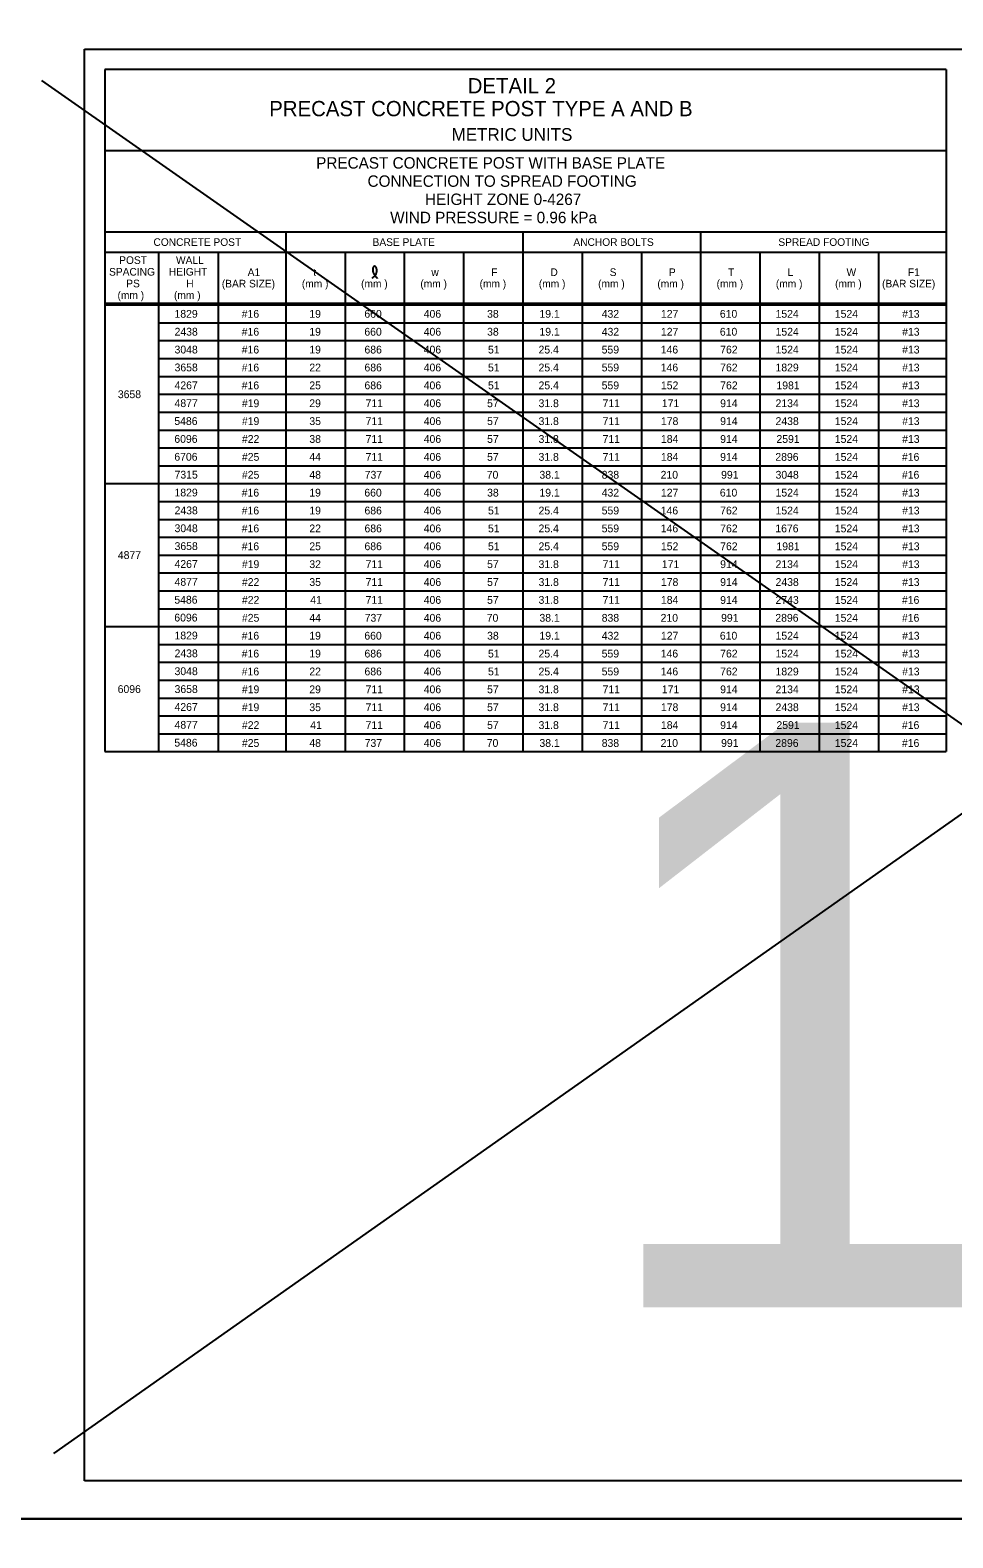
# Model space of a CAD drawing. Extents: x 3351 to 8430, y -3586 to 1457.
# Drawn here: x 5462 to 5825, y -1218 to -624 of the extents above; entities that cross this region are included whole.
import ezdxf

# ---------------------------------------------------------------- set-up
doc = ezdxf.new("R2010")
doc.units = 0
for name, color, linetype in [('1', 7, 'Continuous'), ('2', 7, 'Continuous'), ('PLT-BNDY', 7, 'Continuous')]:
    doc.layers.add(name, color=color, linetype=linetype)

msp = doc.modelspace()

# ---------------------------------------------------------------- linework, layer by layer
at = {"layer": '1'}
for p, q in [((6244.18, -639.77), (5471.21, -1184.55)), ((5491.34, -639.31), (5491.34, -908.06)), ((5822.68, -639.31), (5491.34, -639.31)), ((5822.68, -639.31), (5822.68, -908.06)), ((5466.41, -643.63), (6239.57, -1184.96)), ((5822.68, -671.31), (5491.34, -671.31)), ((5491.34, -703.31), (5822.68, -703.31)), ((5491.34, -703.31), (5559.34, -703.31)), ((5491.34, -703.31), (5559.34, -703.31)), ((5491.34, -703.31), (5559.34, -703.31)), ((5562.68, -703.31), (5562.68, -908.06)), ((5656.01, -703.31), (5656.01, -908.06)), ((5726.01, -703.31), (5726.01, -908.06)), ((5491.34, -711.31), (5822.68, -711.31)), ((5512.68, -908.06), (5512.68, -711.31)), ((5536.01, -711.31), (5536.01, -908.06)), ((5586.01, -711.31), (5586.01, -908.06)), ((5609.34, -711.31), (5609.34, -908.06)), ((5632.68, -711.31), (5632.68, -908.06)), ((5679.34, -711.31), (5679.34, -908.06)), ((5702.68, -711.31), (5702.68, -908.06)), ((5749.34, -711.31), (5749.34, -908.06)), ((5772.68, -711.31), (5772.68, -908.06)), ((5796.01, -711.31), (5796.01, -908.06)), ((5491.34, -731.31), (5822.68, -731.31)), ((5491.34, -732.06), (5822.68, -732.06)), ((5549.33, -735.58), (5549.33, -735.58)), ((5574.34, -735.58), (5574.34, -735.58)), ((5597.68, -735.58), (5597.68, -735.58)), ((5621.01, -735.58), (5621.01, -735.58)), ((5644.34, -735.58), (5644.34, -735.58)), ((5667.68, -735.58), (5667.68, -735.58)), ((5691.01, -735.58), (5691.01, -735.58)), ((5714.34, -735.58), (5714.34, -735.58)), ((5737.67, -735.58), (5737.67, -735.58)), ((5761.01, -735.58), (5761.01, -735.58)), ((5784.34, -735.58), (5784.34, -735.58)), ((5809.33, -735.58), (5809.33, -735.58)), ((5512.68, -739.1), (5822.68, -739.1)), ((5512.68, -746.14), (5822.68, -746.14)), ((5512.68, -753.18), (5822.68, -753.18)), ((5512.68, -760.22), (5822.68, -760.22)), ((5512.68, -767.26), (5822.68, -767.26)), ((5512.68, -774.3), (5822.68, -774.3)), ((5512.68, -781.34), (5822.68, -781.34)), ((5512.68, -788.38), (5822.68, -788.38)), ((5512.68, -795.42), (5822.68, -795.42)), ((5491.34, -802.46), (5822.68, -802.46)), ((5491.34, -802.46), (5822.68, -802.46)), ((5512.68, -809.5), (5822.68, -809.5)), ((5512.68, -816.54), (5822.68, -816.54)), ((5512.68, -823.58), (5822.68, -823.58)), ((5512.68, -830.62), (5822.68, -830.62)), ((5512.68, -837.66), (5822.68, -837.66)), ((5512.68, -844.7), (5822.68, -844.7)), ((5512.68, -851.74), (5822.68, -851.74)), ((5491.34, -858.78), (5822.68, -858.78)), ((5512.68, -865.82), (5822.68, -865.82)), ((5512.68, -872.86), (5822.68, -872.86)), ((5512.68, -879.9), (5822.68, -879.9)), ((5512.68, -886.94), (5822.68, -886.94)), ((5512.68, -893.98), (5822.68, -893.98)), ((5512.68, -901.02), (5822.68, -901.02)), ((5491.34, -908.06), (5822.68, -908.06))]:
    msp.add_line(p, q, dxfattribs=at)
msp.add_spline([(5596.73, -721.48), (5596.94, -721.31), (5597.06, -721.18), (5597.26, -720.98), (5597.42, -720.82), (5597.7, -720.61), (5597.9, -720.35), (5598.08, -720.16), (5598.2, -719.93), (5598.3, -719.68), (5598.38, -719.44), (5598.46, -719.21), (5598.49, -719.02), (5598.52, -718.77), (5598.54, -718.55), (5598.52, -718.3), (5598.48, -718.05), (5598.43, -717.81), (5598.37, -717.58), (5598.28, -717.35), (5598.21, -717.22), (5598.11, -717.12), (5598.02, -717.02), (5597.92, -716.94), (5597.81, -716.88), (5597.72, -716.85), (5597.56, -716.85), (5597.46, -716.88), (5597.31, -716.93), (5597.22, -717.01), (5597.16, -717.1), (5597.09, -717.22), (5597.02, -717.33), (5596.98, -717.47), (5596.95, -717.58), (5596.91, -717.82), (5596.89, -717.99), (5596.91, -718.18), (5596.91, -718.38), (5596.95, -718.66), (5596.97, -718.89), (5597.01, -719.06), (5597.08, -719.28), (5597.18, -719.5), (5597.28, -719.7), (5597.37, -719.9), (5597.49, -720.12), (5597.69, -720.3), (5597.81, -720.51), (5597.94, -720.67), (5598.05, -720.85), (5598.2, -721.02), (5598.33, -721.19), (5598.44, -721.3), (5598.55, -721.43), (5598.66, -721.6)], degree=3, dxfattribs=at)
at = {"layer": '2'}
for p, q in [((5483.34, -1195.31), (5483.34, -631.31)), ((5483.34, -631.31), (6269.34, -631.31)), ((6269.34, -1195.31), (5483.34, -1195.31))]:
    msp.add_line(p, q, dxfattribs=at)
at = {"layer": 'PLT-BNDY'}
for points in [[(5443.34, -616.31), (6284.34, -616.31), (6284.34, -1210.31), (5443.34, -1210.31)], [(5443.34, -1210.31), (6284.34, -1210.31), (6284.34, -1804.31), (5443.34, -1804.31)]]:
    msp.add_lwpolyline(points, close=True, dxfattribs=at)

# ---------------------------------------------------------------- texts
at = {"layer": '1'}
for s, height, p in [('DETAIL 2', 6, (5634.31, -648.71)), ('PRECAST CONCRETE POST TYPE A AND B', 6, (5556.14, -657.71)), ('METRIC UNITS', 5, (5627.97, -667.41)), ('PRECAST CONCRETE POST WITH BASE PLATE', 4.5, (5574.63, -678.36)), ('CONNECTION TO SPREAD FOOTING', 4.5, (5594.86, -685.53)), ('HEIGHT ZONE 0-4267', 4.5, (5617.48, -692.69)), ('WIND PRESSURE = 0.96 kPa', 4.5, (5603.77, -699.86)), ('CONCRETE POST', 3, (5510.55, -708.81)), ('BASE PLATE', 3, (5596.84, -708.81)), ('ANCHOR BOLTS', 3, (5675.91, -708.81)), ('SPREAD FOOTING', 3, (5756.63, -708.81)), ('SPACING', 3, (5493.07, -720.51)), ('POST', 3, (5497.07, -715.91)), ('HEIGHT', 3, (5516.59, -720.51)), ('WALL', 3, (5519.42, -715.91)), ('A1', 3, (5547.64, -720.67)), ('t', 3, (5573.51, -720.67)), ('w', 3, (5619.99, -720.67)), ('F', 3, (5643.6, -720.67)), ('D', 3, (5666.87, -720.67)), ('S', 3, (5690.21, -720.67)), ('P', 3, (5713.54, -720.67)), ('T', 3, (5736.82, -720.67)), ('L', 3, (5760.27, -720.67)), ('W', 3, (5783.48, -720.67)), ('F1', 3, (5807.64, -720.67)), ('PS', 3, (5499.83, -725.11)), ('H', 3, (5523.47, -725.11)), ('(BAR SIZE)', 3, (5537.47, -725.17)), ('(mm )', 3, (5568.98, -725.17)), ('(mm )', 3, (5592.31, -725.17)), ('(mm )', 3, (5615.65, -725.17)), ('(mm )', 3, (5638.98, -725.17)), ('(mm )', 3, (5662.31, -725.17)), ('(mm )', 3, (5685.65, -725.17)), ('(mm )', 3, (5708.98, -725.17)), ('(mm )', 3, (5732.31, -725.17)), ('(mm )', 3, (5755.65, -725.17)), ('(mm )', 3, (5778.98, -725.17)), ('(BAR SIZE)', 3, (5797.47, -725.17)), ('(mm )', 3, (5496.4, -729.71)), ('(mm )', 3, (5518.63, -729.71)), ('1829', 3.07, (5518.84, -737.11)), ('#16', 3.07, (5545.31, -737.11)), ('19', 3.07, (5571.92, -737.11)), ('660', 3.07, (5593.6, -737.11)), ('406', 3.07, (5616.98, -737.11)), ('38', 3.07, (5641.94, -737.11)), ('19.1', 3.07, (5662.55, -737.11)), ('432', 3.07, (5687.07, -737.11)), ('127', 3.07, (5710.4, -737.11)), ('610', 3.07, (5733.6, -737.11)), ('1524', 3.07, (5755.53, -737.11)), ('1524', 3.07, (5778.87, -737.11)), ('#13', 3.07, (5805.39, -737.11)), ('2438', 3.07, (5518.86, -744.15)), ('#16', 3.07, (5545.31, -744.16)), ('19', 3.07, (5571.92, -744.16)), ('660', 3.07, (5593.6, -744.16)), ('406', 3.07, (5616.98, -744.16)), ('38', 3.07, (5641.94, -744.16)), ('19.1', 3.07, (5662.55, -744.16)), ('432', 3.07, (5687.07, -744.16)), ('127', 3.07, (5710.4, -744.16)), ('610', 3.07, (5733.6, -744.16)), ('1524', 3.07, (5755.53, -744.16)), ('1524', 3.07, (5778.87, -744.16)), ('#13', 3.07, (5805.39, -744.16)), ('3048', 3.07, (5518.86, -751.19)), ('#16', 3.07, (5545.31, -751.2)), ('19', 3.07, (5571.92, -751.2)), ('686', 3.07, (5593.65, -751.2)), ('406', 3.07, (5616.98, -751.2)), ('51', 3.07, (5642.29, -751.2)), ('25.4', 3.07, (5662.2, -751.2)), ('559', 3.07, (5687.06, -751.2)), ('146', 3.07, (5710.32, -751.2)), ('762', 3.07, (5733.73, -751.2)), ('1524', 3.07, (5755.53, -751.2)), ('1524', 3.07, (5778.87, -751.2)), ('#13', 3.07, (5805.39, -751.2)), ('3658', 3.07, (5518.86, -758.23)), ('#16', 3.07, (5545.31, -758.25)), ('22', 3.07, (5571.94, -758.25)), ('686', 3.07, (5593.65, -758.25)), ('406', 3.07, (5616.98, -758.25)), ('51', 3.07, (5642.29, -758.25)), ('25.4', 3.07, (5662.2, -758.25)), ('559', 3.07, (5687.06, -758.25)), ('146', 3.07, (5710.32, -758.25)), ('762', 3.07, (5733.73, -758.25)), ('1829', 3.07, (5755.52, -758.25)), ('1524', 3.07, (5778.87, -758.25)), ('#13', 3.07, (5805.39, -758.25)), ('3658', 3.07, (5496.53, -768.79)), ('4267', 3.07, (5518.86, -765.27)), ('#16', 3.07, (5545.31, -765.29)), ('25', 3.07, (5571.94, -765.29)), ('686', 3.07, (5593.65, -765.29)), ('406', 3.07, (5616.98, -765.29)), ('51', 3.07, (5642.29, -765.29)), ('25.4', 3.07, (5662.2, -765.29)), ('559', 3.07, (5687.06, -765.29)), ('152', 3.07, (5710.4, -765.29)), ('762', 3.07, (5733.73, -765.29)), ('1981', 3.07, (5755.88, -765.29)), ('1524', 3.07, (5778.87, -765.29)), ('#13', 3.07, (5805.39, -765.29)), ('4877', 3.07, (5518.86, -772.31)), ('#19', 3.07, (5545.38, -772.34)), ('29', 3.07, (5571.92, -772.34)), ('711', 3.07, (5594.09, -772.34)), ('406', 3.07, (5616.98, -772.34)), ('57', 3.07, (5641.94, -772.34)), ('31.8', 3.07, (5662.2, -772.34)), ('711', 3.07, (5687.42, -772.34)), ('171', 3.07, (5710.75, -772.34)), ('914', 3.07, (5733.73, -772.34)), ('2134', 3.07, (5755.53, -772.34)), ('1524', 3.07, (5778.87, -772.34)), ('#13', 3.07, (5805.39, -772.34)), ('5486', 3.07, (5518.77, -779.35)), ('#19', 3.07, (5545.38, -779.38)), ('35', 3.07, (5571.94, -779.38)), ('711', 3.07, (5594.09, -779.38)), ('406', 3.07, (5616.98, -779.38)), ('57', 3.07, (5641.94, -779.38)), ('31.8', 3.07, (5662.2, -779.38)), ('711', 3.07, (5687.42, -779.38)), ('178', 3.07, (5710.4, -779.38)), ('914', 3.07, (5733.73, -779.38)), ('2438', 3.07, (5755.53, -779.38)), ('1524', 3.07, (5778.87, -779.38)), ('#13', 3.07, (5805.39, -779.38)), ('6096', 3.07, (5518.77, -786.39)), ('#22', 3.07, (5545.39, -786.42)), ('38', 3.07, (5571.94, -786.42)), ('711', 3.07, (5594.09, -786.42)), ('406', 3.07, (5616.98, -786.42)), ('57', 3.07, (5641.94, -786.42)), ('31.8', 3.07, (5662.2, -786.42)), ('711', 3.07, (5687.42, -786.42)), ('184', 3.07, (5710.4, -786.42)), ('914', 3.07, (5733.73, -786.42)), ('2591', 3.07, (5755.88, -786.42)), ('1524', 3.07, (5778.87, -786.42)), ('#13', 3.07, (5805.39, -786.42)), ('6706', 3.07, (5518.77, -793.43)), ('#25', 3.07, (5545.39, -793.47)), ('44', 3.07, (5571.94, -793.47)), ('711', 3.07, (5594.09, -793.47)), ('406', 3.07, (5616.98, -793.47)), ('57', 3.07, (5641.94, -793.47)), ('31.8', 3.07, (5662.2, -793.47)), ('711', 3.07, (5687.42, -793.47)), ('184', 3.07, (5710.4, -793.47)), ('914', 3.07, (5733.73, -793.47)), ('2896', 3.07, (5755.45, -793.47)), ('1524', 3.07, (5778.87, -793.47)), ('#16', 3.07, (5805.31, -793.47)), ('7315', 3.07, (5518.86, -800.47)), ('#25', 3.07, (5545.39, -800.51)), ('48', 3.07, (5571.94, -800.51)), ('737', 3.07, (5593.73, -800.51)), ('406', 3.07, (5616.98, -800.51)), ('70', 3.07, (5641.8, -800.51)), ('38.1', 3.07, (5662.55, -800.51)), ('838', 3.07, (5687.07, -800.51)), ('210', 3.07, (5710.27, -800.51)), ('991', 3.07, (5734.09, -800.51)), ('3048', 3.07, (5755.53, -800.51)), ('1524', 3.07, (5778.87, -800.51)), ('#16', 3.07, (5805.31, -800.51)), ('1829', 3.07, (5518.84, -807.51)), ('#16', 3.07, (5545.31, -807.56)), ('19', 3.07, (5571.92, -807.56)), ('660', 3.07, (5593.6, -807.56)), ('406', 3.07, (5616.98, -807.56)), ('38', 3.07, (5641.94, -807.56)), ('19.1', 3.07, (5662.55, -807.56)), ('432', 3.07, (5687.07, -807.56)), ('127', 3.07, (5710.4, -807.56)), ('610', 3.07, (5733.6, -807.56)), ('1524', 3.07, (5755.53, -807.56)), ('1524', 3.07, (5778.87, -807.56)), ('#13', 3.07, (5805.39, -807.56)), ('2438', 3.07, (5518.86, -814.55)), ('#16', 3.07, (5545.31, -814.6)), ('19', 3.07, (5571.92, -814.6)), ('686', 3.07, (5593.65, -814.6)), ('406', 3.07, (5616.98, -814.6)), ('51', 3.07, (5642.29, -814.6)), ('25.4', 3.07, (5662.2, -814.6)), ('559', 3.07, (5687.06, -814.6)), ('146', 3.07, (5710.32, -814.6)), ('762', 3.07, (5733.73, -814.6)), ('1524', 3.07, (5755.53, -814.6)), ('1524', 3.07, (5778.87, -814.6)), ('#13', 3.07, (5805.39, -814.6)), ('3048', 3.07, (5518.86, -821.59)), ('#16', 3.07, (5545.31, -821.65)), ('22', 3.07, (5571.94, -821.65)), ('686', 3.07, (5593.65, -821.65)), ('406', 3.07, (5616.98, -821.65)), ('51', 3.07, (5642.29, -821.65)), ('25.4', 3.07, (5662.2, -821.65)), ('559', 3.07, (5687.06, -821.65)), ('146', 3.07, (5710.32, -821.65)), ('762', 3.07, (5733.73, -821.65)), ('1676', 3.07, (5755.45, -821.65)), ('1524', 3.07, (5778.87, -821.65)), ('#13', 3.07, (5805.39, -821.65)), ('3658', 3.07, (5518.86, -828.63)), ('#16', 3.07, (5545.31, -828.69)), ('25', 3.07, (5571.94, -828.69)), ('686', 3.07, (5593.65, -828.69)), ('406', 3.07, (5616.98, -828.69)), ('51', 3.07, (5642.29, -828.69)), ('25.4', 3.07, (5662.2, -828.69)), ('559', 3.07, (5687.06, -828.69)), ('152', 3.07, (5710.4, -828.69)), ('762', 3.07, (5733.73, -828.69)), ('1981', 3.07, (5755.88, -828.69)), ('1524', 3.07, (5778.87, -828.69)), ('#13', 3.07, (5805.39, -828.69)), ('4877', 3.07, (5496.53, -832.15)), ('4267', 3.07, (5518.86, -835.67)), ('#19', 3.07, (5545.38, -835.74)), ('32', 3.07, (5571.94, -835.74)), ('711', 3.07, (5594.09, -835.74)), ('406', 3.07, (5616.98, -835.74)), ('57', 3.07, (5641.94, -835.74)), ('31.8', 3.07, (5662.2, -835.74)), ('711', 3.07, (5687.42, -835.74)), ('171', 3.07, (5710.75, -835.74)), ('914', 3.07, (5733.73, -835.74)), ('2134', 3.07, (5755.53, -835.74)), ('1524', 3.07, (5778.87, -835.74)), ('#13', 3.07, (5805.39, -835.74)), ('4877', 3.07, (5518.86, -842.71)), ('#22', 3.07, (5545.39, -842.78)), ('35', 3.07, (5571.94, -842.78)), ('711', 3.07, (5594.09, -842.78)), ('406', 3.07, (5616.98, -842.78)), ('57', 3.07, (5641.94, -842.78)), ('31.8', 3.07, (5662.2, -842.78)), ('711', 3.07, (5687.42, -842.78)), ('178', 3.07, (5710.4, -842.78)), ('914', 3.07, (5733.73, -842.78)), ('2438', 3.07, (5755.53, -842.78)), ('1524', 3.07, (5778.87, -842.78)), ('#13', 3.07, (5805.39, -842.78)), ('5486', 3.07, (5518.77, -849.75)), ('#22', 3.07, (5545.39, -849.82)), ('41', 3.07, (5572.29, -849.82)), ('711', 3.07, (5594.09, -849.82)), ('406', 3.07, (5616.98, -849.82)), ('57', 3.07, (5641.94, -849.82)), ('31.8', 3.07, (5662.2, -849.82)), ('711', 3.07, (5687.42, -849.82)), ('184', 3.07, (5710.4, -849.82)), ('914', 3.07, (5733.73, -849.83)), ('2743', 3.07, (5755.53, -849.83)), ('1524', 3.07, (5778.87, -849.83)), ('#16', 3.07, (5805.31, -849.82)), ('6096', 3.07, (5518.77, -856.79)), ('#25', 3.07, (5545.39, -856.87)), ('44', 3.07, (5571.94, -856.87)), ('737', 3.07, (5593.73, -856.87)), ('406', 3.07, (5616.98, -856.87)), ('70', 3.07, (5641.8, -856.87)), ('38.1', 3.07, (5662.55, -856.87)), ('838', 3.07, (5687.07, -856.87)), ('210', 3.07, (5710.27, -856.87)), ('991', 3.07, (5734.09, -856.87)), ('2896', 3.07, (5755.45, -856.87)), ('1524', 3.07, (5778.87, -856.87)), ('#16', 3.07, (5805.31, -856.87)), ('1829', 3.07, (5518.84, -863.83)), ('#16', 3.07, (5545.31, -863.92)), ('19', 3.07, (5571.92, -863.92)), ('660', 3.07, (5593.6, -863.92)), ('406', 3.07, (5616.98, -863.92)), ('38', 3.07, (5641.94, -863.92)), ('19.1', 3.07, (5662.55, -863.92)), ('432', 3.07, (5687.07, -863.92)), ('127', 3.07, (5710.4, -863.92)), ('610', 3.07, (5733.6, -863.92)), ('1524', 3.07, (5755.53, -863.92)), ('1524', 3.07, (5778.87, -863.92)), ('#13', 3.07, (5805.39, -863.92)), ('2438', 3.07, (5518.86, -870.87)), ('#16', 3.07, (5545.31, -870.96)), ('19', 3.07, (5571.92, -870.96)), ('686', 3.07, (5593.65, -870.96)), ('406', 3.07, (5616.98, -870.96)), ('51', 3.07, (5642.29, -870.96)), ('25.4', 3.07, (5662.2, -870.96)), ('559', 3.07, (5687.06, -870.96)), ('146', 3.07, (5710.32, -870.96)), ('762', 3.07, (5733.73, -870.96)), ('1524', 3.07, (5755.53, -870.96)), ('1524', 3.07, (5778.87, -870.96)), ('#13', 3.07, (5805.39, -870.96)), ('3048', 3.07, (5518.86, -877.91)), ('#16', 3.07, (5545.31, -878.01)), ('22', 3.07, (5571.94, -878.01)), ('686', 3.07, (5593.65, -878.01)), ('406', 3.07, (5616.98, -878.01)), ('51', 3.07, (5642.29, -878.01)), ('25.4', 3.07, (5662.2, -878.01)), ('559', 3.07, (5687.06, -878.01)), ('146', 3.07, (5710.32, -878.01)), ('762', 3.07, (5733.73, -878.01)), ('1829', 3.07, (5755.52, -878.01)), ('1524', 3.07, (5778.87, -878.01)), ('#13', 3.07, (5805.39, -878.01)), ('6096', 3.07, (5496.45, -884.95)), ('3658', 3.07, (5518.86, -884.95)), ('#19', 3.07, (5545.38, -885.05)), ('29', 3.07, (5571.92, -885.05)), ('711', 3.07, (5594.09, -885.05)), ('406', 3.07, (5616.98, -885.05)), ('57', 3.07, (5641.94, -885.05)), ('31.8', 3.07, (5662.2, -885.05)), ('711', 3.07, (5687.42, -885.05)), ('171', 3.07, (5710.75, -885.05)), ('914', 3.07, (5733.73, -885.05)), ('2134', 3.07, (5755.53, -885.05)), ('1524', 3.07, (5778.87, -885.05)), ('#13', 3.07, (5805.39, -885.05)), ('4267', 3.07, (5518.86, -891.99)), ('#19', 3.07, (5545.38, -892.1)), ('35', 3.07, (5571.94, -892.1)), ('711', 3.07, (5594.09, -892.1)), ('406', 3.07, (5616.98, -892.1)), ('57', 3.07, (5641.94, -892.1)), ('31.8', 3.07, (5662.2, -892.1)), ('711', 3.07, (5687.42, -892.1)), ('178', 3.07, (5710.4, -892.1)), ('914', 3.07, (5733.73, -892.1)), ('2438', 3.07, (5755.53, -892.1)), ('1524', 3.07, (5778.87, -892.1)), ('#13', 3.07, (5805.39, -892.1)), ('4877', 3.07, (5518.86, -899.03)), ('#22', 3.07, (5545.39, -899.14)), ('41', 3.07, (5572.29, -899.14)), ('711', 3.07, (5594.09, -899.14)), ('406', 3.07, (5616.98, -899.14)), ('57', 3.07, (5641.94, -899.14)), ('31.8', 3.07, (5662.2, -899.14)), ('711', 3.07, (5687.42, -899.14)), ('12', 230.4, (5680, -1127.02)), ('184', 3.07, (5710.4, -899.14)), ('914', 3.07, (5733.73, -899.14)), ('2591', 3.07, (5755.88, -899.14)), ('1524', 3.07, (5778.87, -899.14)), ('#16', 3.07, (5805.31, -899.14)), ('5486', 3.07, (5518.77, -906.07)), ('#25', 3.07, (5545.39, -906.19)), ('48', 3.07, (5571.94, -906.19)), ('737', 3.07, (5593.73, -906.19)), ('406', 3.07, (5616.98, -906.19)), ('70', 3.07, (5641.8, -906.19)), ('38.1', 3.07, (5662.55, -906.19)), ('838', 3.07, (5687.07, -906.19)), ('210', 3.07, (5710.27, -906.19)), ('991', 3.07, (5734.09, -906.19)), ('2896', 3.07, (5755.45, -906.19)), ('1524', 3.07, (5778.87, -906.19)), ('#16', 3.07, (5805.31, -906.19))]:
    msp.add_text(s, height=height, dxfattribs=at).set_placement(p)

doc.saveas('drawing.dxf')
